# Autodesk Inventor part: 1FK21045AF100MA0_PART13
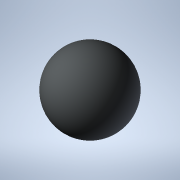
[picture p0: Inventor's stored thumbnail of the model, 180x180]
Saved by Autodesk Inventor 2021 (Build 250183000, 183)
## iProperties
Created: 2025-04
Part Number: 1FK21045AF100MA0_PART13
Material: Generic
Catalog Web Link: www.3dfindit.com
Description: -Servo synchronous motor
Document SubType Name: Modeling
Designer: psAdmin
Mass: 0.137258 g
Surface Area: 1.2868 cm^2
Volume: 0.137258 cm^3
Density: 1 g/cm^3
Appearance: PSOLRGB-212-217-219
Category: PARTsolutions
Title: 1FK21045AF100MA0_PART13
Author: Cadenas PARTsolutions
Comments: Servo synchronous motor
Sending System: PARTsolutions
Preprocessor: ST-DEVELOPER v19.3
PSOL_IDENT_0: {$CADENAS_DATA/23d-libs/siemens_ag/_cat_/52/6b/1fk21045af100ma0.prj},216 {VTYP=3D},{NB=1FK21045AF100
PSOL_IDENT_1: MA0_PART13},{LINA=1FK21045AF100MA0_PART13},{NN=1FK21045AF100MA0_PART13},{NOPRJ=TRUE},{DATE=19.08.202
PSOL_IDENT_2: 5 14:00:38},{GEOMDATE=30.07.2025 02:01:45},{VERSION=},{LINEID=10},{WBVAR=},{WBNUMERIC=}  {NB=1FK2104
PSOL_IDENT_3: 5AF100MA0_PART13},{LINA=1FK21045AF100MA0_PART13},{KT=DUMMY},{PREVIEW=../../../_pool_/cb/72/p_d211_xx
PSOL_IDENT_4: _00434j.png},{DESCSHORT=SIMOTICS S-1FK2 HD, SINAMICS S210 3AC 400V-480V, 2.4 Nm, 3000 rpm},{DESCLONG=
PSOL_IDENT_5: SIMOTICS S-1FK2 HD servo motor M0=2.4 Nm; PN = 0.75 kW at nN=3000 rpm (380-480 V); PN = 0.375 kW at
PSOL_IDENT_6: nN=1500 rpm (200-240 V); with holding brake; degree of protection IP64; cylindrical shaft D19x40mm;
PSOL_IDENT_7: absolute encoder 22-bit + 12-bit multiturn (encoder AM22DQC); with OCC interface; plug size M17, rot
PSOL_IDENT_8: atable; SIMOTICS S-1FK2 servomotorfor a wide range of uses in industrial environments. SIMOTICS S‑1F
PSOL_IDENT_9: K2 servomotors are compact synchronous motors with a high dynamic performance that set themselves ap
PSOL_IDENT_10: art as a result of their high power density, degree of protection and overload capability. The motor
PSOL_IDENT_11: s are available in two variants: as High Dynamic variant (highest dynamic performance as a result of
PSOL_IDENT_12: the low intrinsic moment of inertia for applications demanding a high dynamic performance with low
PSOL_IDENT_13: moved masses) - and as Compact variant (precise and stable closed-loop control for medium up to larg
PSOL_IDENT_14: e moved masses as a result of a medium intrinsic moment of inertia). SIMOTICSS‑1FK2 servomotors full
PSOL_IDENT_15: y exploit their strengths in a system with the SINAMICSS210 frequency converter and simple connectio
PSOL_IDENT_16: n using the one cable connection (OCC). Advantages include the short control and positioning times,
PSOL_IDENT_17: fast and precise correction of disturbing quantities as well as stable control with a high dynamic p
PSOL_IDENT_18: erformance. The servo motors can be configured to address a wide range of requirements. For example
PSOL_IDENT_19: with and without holding brake, IP64 or IP65 degree of protection, singleturn or multiturn absolute
PSOL_IDENT_20: encoders - to name just a few. Further, the servomotors are available in different shaft heights ext
PSOL_IDENT_21: ending from 20 to 100. A shaft sealing ring is available to achieve an IP65 degree of protection and
PSOL_IDENT_22: for subsequent mounting at the motor or as spare part. SIMOTICS - the optimum motor for each and ev
PSOL_IDENT_23: ery motion control application.},{INTNO=804766906411},{SUPPLIERALTNO=1FK2104-5AF10-0MA0},{MANUID=1FK
PSOL_IDENT_24: 21045AF100MA0},{MANUNAME=Siemens},{MANUTYPEDESC=Synchronous motor 1FK2-HD 2.4 NM},{AAU732=SIMOTICS},
PSOL_IDENT_25: {AAO057=S-1FK2},{AAU734=SIMOTICS S-1FK2 HD servo motor M0=2.4 Nm; PN = 0.75 kW at nN=3000 rpm (380-4
PSOL_IDENT_26: 80 V); PN = 0.375 kW at nN=1500 rpm (200-240 V); with holding brake; degree of protection IP64; cyli
PSOL_IDENT_27: ndrical shaft D19x40mm; absolute encoder 22-bit + 12-bit multiturn (encoder AM22DQC); with OCC inter
PSOL_IDENT_28: face; plug size M17, rotatable;},{AAW338=Synchronous motor 1FK2-HD 2.4 NM},{AAO742=SIMOTICS},{AAO663=
PSOL_IDENT_29: 4042948693070},{NOCUPEROU=1},{PRICEQUANTITY=1},{QUANTITYMIN=1},{QUANTITYINT=1},{CTN=85015100},{COO=D
PSOL_IDENT_30: E},{AAO676=1FK2104-5AF10-0MA0},{AAO677=Siemens AG},{ORDERUNIT=C62},{CONTENTUNIT=C62}
NB: 1FK21045AF100MA0_PART13
NT: Servo synchronous motor
NBSYN: $MANUID._PART13
LINA: 1FK21045AF100MA0_PART13
CATALOG: SIEMENS
PREVIEW: ../../../_pool_/cb/72/p_d211_xx_00434j.png
DESCSHORT: SIMOTICS S-1FK2 HD, SINAMICS S210 3AC 400V-480V, 2.4 Nm, 3000 rpm
DESCLONG: SIMOTICS S-1FK2 HD servo motor M0=2.4 Nm; PN = 0.75 kW at nN=3000 rpm (380-480 V); PN = 0.375 kW at nN=1500 rpm (200-240 V); with holding brake; degree of prote
INTNO: 804766906411
SUPPLIERALTNO: 1FK2104-5AF10-0MA0
MANUID: 1FK21045AF100MA0
MANUNAME: Siemens
MANUTYPEDESC: Synchronous motor 1FK2-HD 2.4 NM
AAU732: SIMOTICS
AAO057: S-1FK2
AAU734: SIMOTICS S-1FK2 HD servo motor M0=2.4 Nm; PN = 0.75 kW at nN=3000 rpm (380-480 V); PN = 0.375 kW at nN=1500 rpm (200-240 V); with holding brake; degree of prote
AAW338: Synchronous motor 1FK2-HD 2.4 NM
AAO742: SIMOTICS
AAO663: 4042948693070.0
NOCUPEROU: 1
PRICEQUANTITY: 1
QUANTITYMIN: 1
QUANTITYINT: 1
CTN: 85015100
COO: DE
ARTICLENO: 1FK21045AF100MA0_PART13
BOMINFO: 1FK21045AF100MA0_PART13
CREATOR: CADENAS GmbH
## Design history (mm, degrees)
feature "2025_04_17_15_34_52_0317"
body "Solid1"
